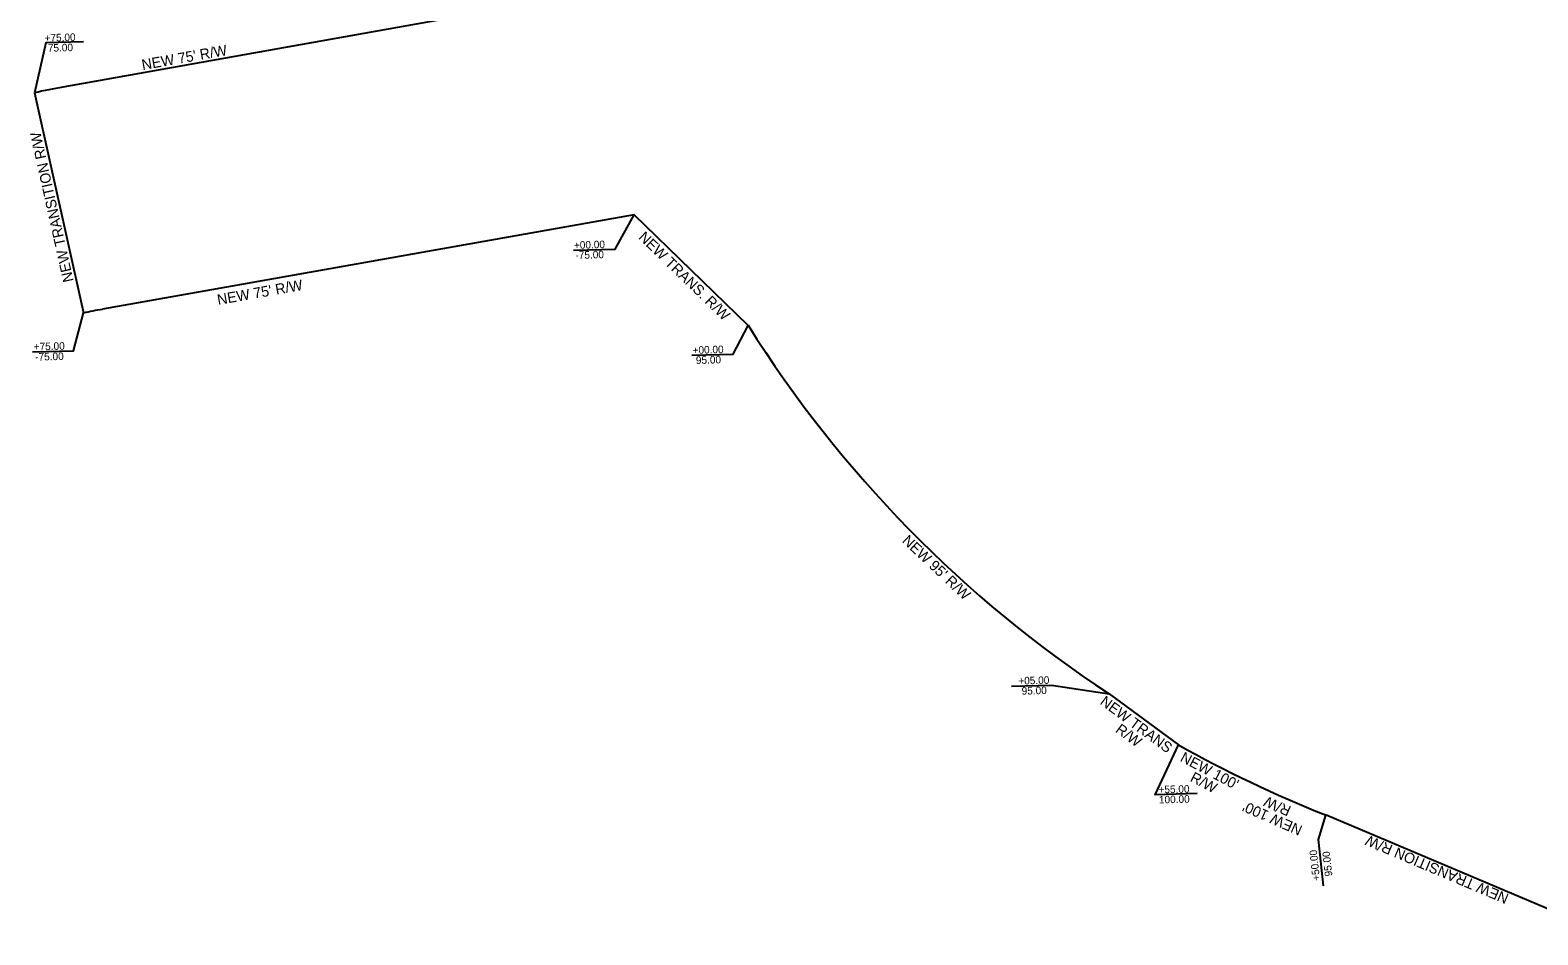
# Model space of a CAD drawing. Extents: x 2003184 to 2010449, y 855784 to 861212.
# Drawn here: x 2003184 to 2004187, y 857577 to 858179 of the extents above; entities that cross this region are included whole.
import ezdxf

# ---------------------------------------------------------------- set-up
doc = ezdxf.new("R2010")
doc.units = 0
doc.layers.add('RD_PD_RW', color=7, linetype='Continuous')
doc.layers.add('RD_PD_RW_TX', color=7, linetype='Continuous')

msp = doc.modelspace()

# ---------------------------------------------------------------- linework, layer by layer
at = {"layer": 'RD_PD_RW'}
for p, q in [((2003485.9, 858190.6), (2003206.3, 858140.9)), ((2003187.4, 858137.1), (2003220, 857990.7)), ((2003586, 858056), (2003232.5, 857993.2)), ((2003661.9, 857982.5), (2003586, 858056)), ((2003902, 857737.5), (2003948, 857703.7)), ((2004234.6, 857577.4), (2004045.8, 857657.2))]:
    msp.add_line(p, q, dxfattribs=at)
for centre, radius, start, end in [((2003284.3, 857701.7), 446, 100.0794, 102.5532), ((2003284.3, 857701.7), 296, 100.0794, 102.5532), ((2004344.4, 858411.2), 806, 212.13, 236.7083), ((2004344.4, 858411.2), 811, 240.7376, 248.3931)]:
    msp.add_arc(centre, radius, start, end, dxfattribs=at)
at = {"layer": 'RD_PD_RW_TX'}
for points in [[(2003219.9, 858170.9), (2003194.9, 858170.2), (2003187.4, 858137.1)], [(2003545.7, 858032.4), (2003573.4, 858033.2), (2003586, 858056)], [(2003186.1, 857964.9), (2003213.2, 857965.6), (2003220, 857990.7)], [(2003624.5, 857962.6), (2003651.9, 857963.4), (2003661.9, 857982.5)], [(2003836.9, 857742.7), (2003863.7, 857743.4), (2003902, 857737.5)], [(2003960.5, 857671.3), (2003932.6, 857670.5), (2003948, 857703.7)], [(2004044.4, 857610), (2004041.1, 857640.7), (2004046.1, 857657)]]:
    msp.add_lwpolyline(points, dxfattribs=at)

# ---------------------------------------------------------------- texts
for s, height, rotation, p in [('+75.00', 5, 1.6093, (2003194.1, 858171)), ('75.00', 5, 1.6093, (2003196.3, 858164.3)), ("NEW 75' R/W", 7, 10.0794, (2003259.3, 858152.1)), ('NEW TRANSITION R/W', 7, 102.5532, (2003213.4, 858012)), ('NEW TRANS. R/W', 7, 315.9295, (2003588.5, 858040.5)), ('+00.00', 5, 1.6093, (2003546.1, 858033.3)), ('-75.00', 5, 1.6093, (2003547.1, 858026.6)), ("NEW 75' R/W", 7, 10.0794, (2003309.5, 857996)), ('+75.00', 5, 1.6093, (2003186.9, 857965.8)), ('+00.00', 5, 1.6093, (2003625, 857963.5)), ('-75.00', 5, 1.6093, (2003187.9, 857959)), ('95.00', 5, 1.6093, (2003627.2, 857956.8)), ("NEW 95' R/W", 7, 316.8229, (2003763.8, 857838.7)), ('+05.00', 5, 1.6093, (2003841.6, 857743.7)), ('95.00', 5, 1.6093, (2003843.8, 857737)), ('NEW TRANS', 7, 323.6993, (2003895.3, 857731.1)), ('R/W', 7, 323.6993, (2003905.6, 857712.6)), ("NEW 100'", 7, 332.3748, (2003948.6, 857693.1)), ('R/W', 7, 332.3748, (2003955.2, 857679.8)), ('+55.00', 5, 1.6093, (2003934.8, 857671.4)), ('100.00', 5, 1.6093, (2003935.1, 857664.7)), ("NEW 100'", 7, 156.1777, (2004031, 857649.5)), ('R/W', 7, 156.1777, (2004023.5, 857662.4)), ('NEW TRANSITION R/W', 7, 157.0921, (2004168.2, 857604.2)), ('+50.00', 5, 96.1251, (2004042.2, 857613.6)), ('95.00', 5, 96.1251, (2004050.4, 857616.5))]:
    msp.add_text(s, height=height, rotation=rotation, dxfattribs=at).set_placement(p)

doc.saveas('drawing.dxf')
